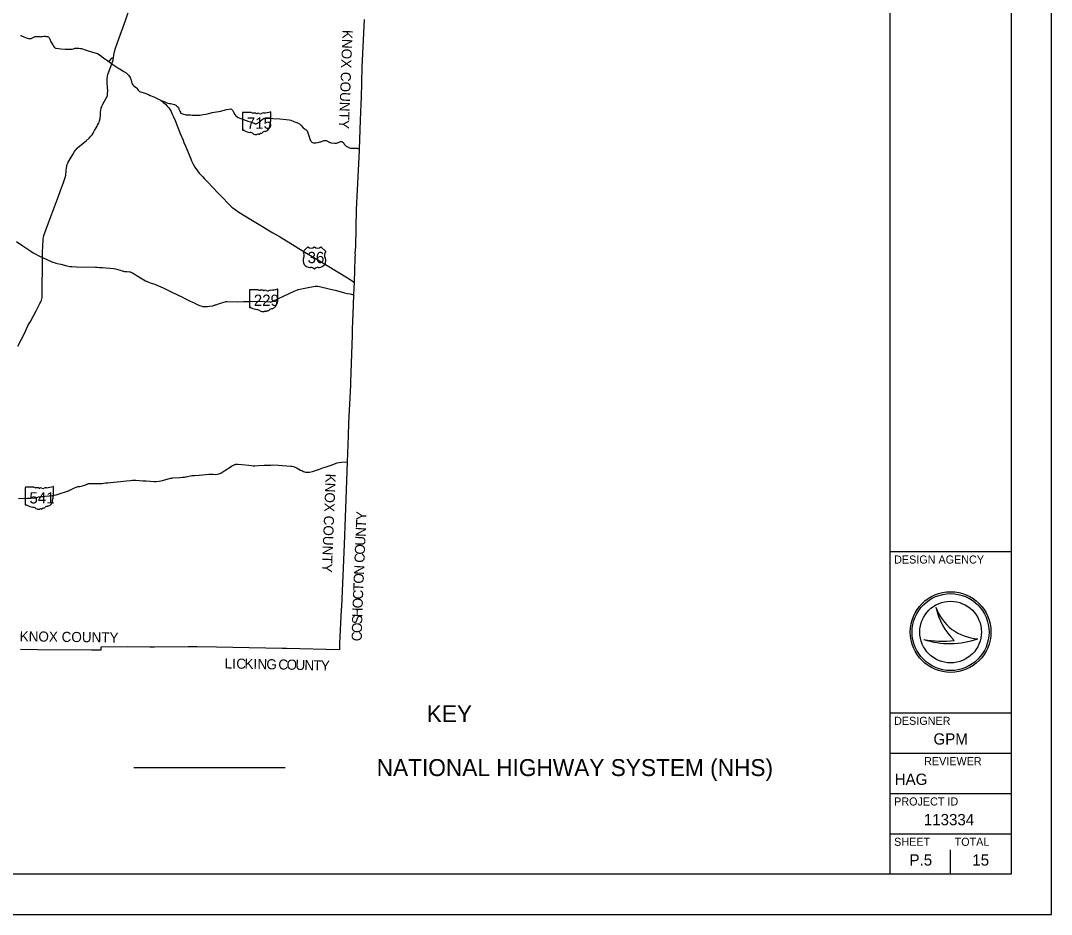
# Model space of a CAD drawing. Extents: x 1851937 to 2123937, y 78841 to 965467.
# Drawn here: x 2021685 to 2123937, y 789467 to 878119 of the extents above; entities that cross this region are included whole.
import ezdxf

# ---------------------------------------------------------------- set-up
doc = ezdxf.new("R2010")
doc.units = 0
for name, color, linetype in [('GM_X_County', 7, 'Continuous'), ('GM_X_County_Text', 7, 'Continuous'), ('GM_X_State_Location', 7, 'Continuous'), ('GM_X_State_Route', 7, 'Continuous'), ('GM_X_State_Shield', 7, 'Continuous'), ('GM_X_US_Location', 7, 'Continuous'), ('GM_X_US_Route', 7, 'Continuous'), ('GM_X_US_Shield', 7, 'Continuous'), ('SH_Border', 7, 'Continuous'), ('SH_Cut_Line', 7, 'Continuous'), ('SH_Data', 7, 'Continuous'), ('UT_P_Electric', 7, 'Continuous')]:
    doc.layers.add(name, color=color, linetype=linetype)

msp = doc.modelspace()

# ---------------------------------------------------------------- linework, layer by layer
at = {"layer": 'GM_X_County'}
msp.add_lwpolyline([(2055763, 878218), (2055528, 873511), (2055458, 870451), (2055436, 869891), (2055434, 869842), (2055375, 868236), (2055262, 865369), (2055260, 865250), (2054985, 859397), (2054895, 855723), (2054855, 855032), (2054877, 854884), (2054856, 854579), (2054855, 854554), (2054764, 852183), (2054712, 850926), (2054638, 848994), (2054606, 848369), (2054607, 848277), (2054583, 847562), (2054568, 846927), (2054408, 842255), (2054398, 841945), (2054221, 838228), (2054174, 836926), (2054094, 834355), (2053973, 831537), (2053891, 828875), (2053767, 826144), (2053518, 820007), (2053497, 819709), (2053322, 816320), (2053316, 815692), (2048065, 815838), (2047645, 815846), (2042723, 815938), (2041129, 815964), (2039196, 815994), (2038297, 816009), (2034983, 815969), (2034492, 815973), (2032252, 815993), (2029642, 815987), (2029630, 815668), (2029367, 815674), (2028708, 815664), (2023355, 815717), (2021673, 815746)], dxfattribs=at)
at = {"layer": 'GM_X_State_Route'}
msp.add_line((2052003, 866233), (2052042, 866219), dxfattribs=at)
for points in [[(2035622, 870200), (2035980, 870055), (2036138, 869993), (2036279, 869945), (2036417, 869913), (2036558, 869892), (2036695, 869872), (2036812, 869847), (2036953, 869792), (2037068, 869733), (2037193, 869644), (2037289, 869554), (2037333, 869488), (2037394, 869337), (2037480, 869134), (2037541, 869022), (2037562, 868988), (2037591, 868947), (2037634, 868917), (2037676, 868894), (2037828, 868834), (2037993, 868797), (2038083, 868790), (2038305, 868768), (2038542, 868758), (2038695, 868755), (2039115, 868743), (2039321, 868736), (2039479, 868750), (2039806, 868794), (2040101, 868837), (2040308, 868894), (2040463, 868945), (2040583, 868978), (2040689, 868997), (2040897, 869025), (2041337, 869092), (2041531, 869128), (2041735, 869189), (2041920, 869248), (2042003, 869277), (2042114, 869305), (2042363, 869352), (2042545, 869368)], [(2042545, 869368), (2042594, 869335), (2042642, 869290), (2042692, 869229), (2042775, 869098), (2042941, 868820), (2043046, 868684), (2043125, 868603), (2043165, 868565), (2043271, 868507), (2043441, 868437), (2043799, 868311), (2044072, 868207), (2044145, 868174)], [(2044145, 868174), (2044228, 868146), (2044485, 868066), (2044650, 868020), (2044748, 867974), (2044966, 867882), (2045049, 867884), (2045115, 867905), (2045347, 868044), (2045496, 868148), (2045657, 868302), (2045738, 868374), (2045780, 868397), (2045815, 868412), (2045863, 868423), (2045947, 868426), (2046333, 868432), (2046443, 868437), (2046694, 868418), (2047415, 868366), (2048030, 868319), (2048311, 868286), (2048478, 868237), (2048778, 868099), (2048964, 868039), (2049141, 867976), (2049274, 867922), (2049359, 867871), (2049472, 867746), (2049726, 867482), (2049814, 867406), (2049915, 867340), (2050017, 867279), (2050061, 867246), (2050096, 867193), (2050135, 867079), (2050331, 866489), (2050383, 866338), (2050436, 866237), (2050475, 866182), (2050522, 866127), (2050584, 866072), (2050651, 866031), (2050728, 866006), (2050822, 865996), (2050879, 865998), (2050960, 866010), (2051306, 866077), (2051387, 866092), (2051453, 866112), (2051589, 866162), (2051710, 866205), (2051772, 866223), (2051831, 866236), (2051890, 866242), (2051958, 866240), (2052003, 866233)], [(2052042, 866219), (2052077, 866207), (2052132, 866177), (2052188, 866133), (2052226, 866106), (2052260, 866081), (2052309, 866057), (2052356, 866039), (2052403, 866025), (2052481, 866008), (2052812, 865968), (2052913, 865962), (2052979, 865966), (2053034, 865976), (2053116, 865997), (2053426, 866114), (2053479, 866122), (2053566, 866119), (2053626, 866069), (2053679, 866020), (2053734, 865955), (2053794, 865862), (2053875, 865765), (2053976, 865673), (2054118, 865595), (2054322, 865511), (2054443, 865484), (2054558, 865484), (2054697, 865479), (2054909, 865475), (2055012, 865470), (2055069, 865457), (2055134, 865442), (2055263, 865366)], [(2021285, 856194), (2021906, 855784), (2022683, 855235), (2022919, 855090), (2023123, 854987), (2023488, 854802), (2023844, 854619)], [(2023844, 854619), (2024790, 854189), (2024894, 854148), (2025009, 854111), (2025183, 854074), (2025303, 854043), (2025690, 853958), (2026273, 853807), (2026552, 853731), (2026625, 853722), (2026751, 853716), (2027226, 853703), (2029102, 853652), (2029292, 853649)], [(2029292, 853649), (2029522, 853642), (2029816, 853631), (2030924, 853540), (2031100, 853511), (2031577, 853355), (2031749, 853299), (2031907, 853260), (2031995, 853249), (2032223, 853231), (2032440, 853215), (2032465, 853231), (2032563, 853189), (2032633, 853168), (2032697, 853141), (2032773, 853106), (2032940, 853009), (2033160, 852878), (2033740, 852518), (2034066, 852310), (2034317, 852203), (2034631, 852090), (2034990, 851965), (2035205, 851885), (2035600, 851702), (2035822, 851600), (2036739, 851166), (2037747, 850679), (2037983, 850558), (2038310, 850375), (2038448, 850310), (2038748, 850177), (2038912, 850117), (2039196, 849977), (2039309, 849934), (2039428, 849865), (2039572, 849817), (2039718, 849779), (2039844, 849748), (2040005, 849748), (2040213, 849751), (2040464, 849784), (2040747, 849839), (2041001, 849914), (2041048, 849930), (2041401, 850045), (2041852, 850201), (2041963, 850234), (2042035, 850243), (2042166, 850249), (2043216, 850231), (2043791, 850266), (2043860, 850260), (2044148, 850272), (2044402, 850274), (2045208, 850282), (2045895, 850266), (2046400, 850216), (2046520, 850227), (2046586, 850240), (2046717, 850278), (2048813, 851279), (2049136, 851424), (2049202, 851449), (2049254, 851457), (2049547, 851531), (2050057, 851624), (2050901, 851771), (2051075, 851783), (2051166, 851780), (2051337, 851749), (2052303, 851516), (2053025, 851339), (2053826, 851132), (2054114, 851058), (2054374, 851004), (2054713, 850923)], [(2029952, 832238), (2030108, 832256), (2030346, 832282), (2030597, 832307), (2031592, 832399), (2032180, 832461), (2032572, 832505), (2032800, 832522), (2032958, 832528), (2033117, 832530), (2033841, 832480), (2034136, 832461), (2034924, 832412), (2035163, 832410), (2035426, 832426), (2035761, 832494), (2036549, 832724), (2036702, 832748), (2036773, 832755), (2037484, 832806), (2037755, 832831), (2037951, 832850), (2038057, 832865), (2038195, 832895), (2038244, 832916), (2038536, 832971), (2038663, 832988), (2038861, 833008), (2038943, 833011), (2039387, 833039), (2040347, 833121), (2040792, 833119), (2040992, 833115), (2041217, 833138), (2041356, 833181), (2041442, 833206), (2041535, 833241), (2041735, 833349), (2042051, 833548), (2042460, 833818), (2042620, 833921), (2042711, 833981), (2042802, 834029), (2042869, 834062), (2042946, 834091), (2042980, 834103), (2043026, 834112), (2043117, 834118), (2043221, 834116), (2043634, 834075), (2044325, 834014), (2044549, 833991), (2044751, 833969), (2044931, 833965), (2045285, 833980), (2045854, 834016), (2046037, 834022), (2046308, 834034), (2046496, 834041), (2046698, 834045), (2047274, 834013), (2048444, 833936), (2048591, 833916), (2048718, 833892), (2048815, 833859), (2048914, 833819), (2049105, 833723), (2049296, 833623), (2049459, 833538), (2049642, 833451), (2049753, 833395), (2049838, 833365), (2049936, 833340), (2050041, 833326), (2050246, 833322), (2050341, 833331), (2050634, 833403), (2050835, 833470), (2051332, 833641), (2051649, 833755), (2051987, 833864), (2052501, 834035), (2053071, 834242), (2053272, 834299), (2053515, 834326), (2054095, 834352)], [(2021483, 830726), (2022343, 830751), (2022732, 830765), (2023046, 830784), (2023208, 830800), (2023489, 830872), (2023575, 830891), (2023687, 830908), (2023902, 830930), (2024112, 830941), (2024521, 830974), (2024839, 831012), (2025024, 831043), (2025228, 831086), (2025719, 831239), (2026154, 831378), (2026426, 831471), (2026582, 831537), (2027027, 831764)], [(2027027, 831764), (2027032, 831766), (2027197, 831849), (2027294, 831888), (2027353, 831903), (2027427, 831912), (2027560, 831920), (2027694, 831939), (2027839, 831969), (2028042, 832039), (2028415, 832198), (2028477, 832212), (2028581, 832220), (2028628, 832220), (2028803, 832220)], [(2028803, 832220), (2028974, 832217), (2029145, 832214), (2029319, 832215), (2029475, 832212), (2029785, 832219), (2029952, 832238)]]:
    msp.add_lwpolyline(points, dxfattribs=at)
at = {"layer": 'GM_X_State_Shield'}
for p, q in [((2043700, 868973), (2043700, 867272)), ((2044548, 869002), (2043727, 869002)), ((2046501, 868155), (2046501, 869045)), ((2046501, 868155), (2046501, 868155)), ((2044401, 851401), (2044401, 849699)), ((2045249, 851430), (2044428, 851430)), ((2047202, 850582), (2047202, 851472)), ((2047202, 850582), (2047202, 850582)), ((2022147, 831806), (2022147, 830105)), ((2022996, 831836), (2022175, 831836)), ((2024949, 830988), (2024949, 831878)), ((2024949, 830988), (2024949, 830988))]:
    msp.add_line(p, q, dxfattribs=at)
for centre, major_axis, start_param, end_param in [((2043732, 868977), (32.5, 0), 1.7126934, 3.2834897), ((2044743, 869200), (315, 0), 4.042523, 4.731795), ((2044848, 868047), (1130, 0), 1.4047578, 1.6578581), ((2045104, 868986), (90.8, 0), 3.8360951, 5.1854146), ((2045237, 868789), (189, 0), 0.950623, 2.079405), ((2045481, 869059), (227, 0), 4.0815608, 5.1457227), ((2045882, 868483), (598, 0), 1.6990114, 2.1078141), ((2045503, 871322), (2971, 0), 4.8143942, 5.0423688), ((2046494, 868089), (48.3, 0), 1.8839779, 3.6710726), ((2046470, 869048), (31.2, 0), 6.1411519, 7.9890352), ((2046468, 868151), (33.4, 0), 5.05454, 6.4181714), ((2043732, 867268), (32.7, 0), 3.00124, 4.5083009), ((2043737, 867442), (250, 0), 4.6659457, 4.8974612), ((2043788, 867174), (90.1, 0), 0.5192072, 1.6278991), ((2044926, 868702), (2146, 0), 4.1959971, 4.4889607), ((2045983, 866794), (407, 0), 1.6476453, 2.4884337), ((2045670, 867669), (743, 0), 5.1017525, 6.4400178), ((2046613, 867782), (211, 0), 2.3877238, 3.2625369), ((2046187, 867977), (290, 0), 5.9346948, 6.6959481), ((2044286, 866508), (671, 0), 0.8235189, 1.3235874), ((2045012, 867165), (426, 0), 4.0264811, 4.9967352), ((2045258, 866577), (350, 0), 1.495662, 1.9409797), ((2045289, 867038), (227, 0), 4.6910439, 5.5073738), ((2045495, 866873), (63.9, 0), 1.1475842, 2.3151517), ((2045468, 867107), (240, 0), 4.9370686, 5.64225), ((2044433, 851404), (32.5, 0), 1.7126934, 3.2834897), ((2045444, 851627), (315, 0), 4.042523, 4.731795), ((2045548, 850475), (1130, 0), 1.4047578, 1.6578581), ((2045805, 851413), (90.8, 0), 3.8360951, 5.1854146), ((2045938, 851216), (189, 0), 0.950623, 2.079405), ((2046182, 851486), (227, 0), 4.0815608, 5.1457227), ((2046583, 850910), (598, 0), 1.6990114, 2.1078141), ((2046204, 853749), (2971, 0), 4.8143942, 5.0423688), ((2047171, 851476), (31.2, 0), 6.1411519, 7.9890352), ((2046371, 850097), (743, 0), 5.1017525, 6.4400178), ((2047314, 850210), (211, 0), 2.3877238, 3.2625369), ((2047195, 850517), (48.3, 0), 1.8839779, 3.6710726), ((2046888, 850404), (290, 0), 5.9346948, 6.6959481), ((2047169, 850579), (33.4, 0), 5.05454, 6.4181714), ((2044433, 849696), (32.7, 0), 3.00124, 4.5083009), ((2044438, 849870), (250, 0), 4.6659457, 4.8974612), ((2044489, 849601), (90.1, 0), 0.5192072, 1.6278991), ((2045627, 851130), (2146, 0), 4.1959971, 4.4889607), ((2044987, 848935), (671, 0), 0.8235189, 1.3235874), ((2045713, 849593), (426, 0), 4.0264811, 4.9967352), ((2045959, 849005), (350, 0), 1.495662, 1.9409797), ((2045990, 849465), (227, 0), 4.6910439, 5.5073738), ((2046196, 849301), (63.9, 0), 1.1475842, 2.3151517), ((2046168, 849535), (240, 0), 4.9370686, 5.64225), ((2046684, 849222), (407, 0), 1.6476453, 2.4884337), ((2022180, 831810), (32.5, 0), 1.7126934, 3.2834897), ((2023191, 832033), (315, 0), 4.042523, 4.731795), ((2023295, 830881), (1130, 0), 1.4047578, 1.6578581), ((2023552, 831819), (90.8, 0), 3.8360951, 5.1854146), ((2023685, 831622), (189, 0), 0.950623, 2.079405), ((2023929, 831892), (227, 0), 4.0815608, 5.1457227), ((2024330, 831316), (598, 0), 1.6990114, 2.1078141), ((2023951, 834155), (2971, 0), 4.8143942, 5.0423688), ((2024918, 831882), (31.2, 0), 6.1411519, 7.9890352), ((2024118, 830502), (743, 0), 5.1017525, 6.4400178), ((2025061, 830616), (211, 0), 2.3877238, 3.2625369), ((2024942, 830923), (48.3, 0), 1.8839779, 3.6710726), ((2024635, 830810), (290, 0), 5.9346948, 6.6959481), ((2024916, 830985), (33.4, 0), 5.05454, 6.4181714), ((2022180, 830102), (32.7, 0), 3.00124, 4.5083009), ((2022185, 830276), (250, 0), 4.6659457, 4.8974612), ((2022236, 830007), (90.1, 0), 0.5192072, 1.6278991), ((2023374, 831536), (2146, 0), 4.1959971, 4.4889607), ((2022734, 829341), (671, 0), 0.8235189, 1.3235874), ((2023460, 829999), (426, 0), 4.0264811, 4.9967352), ((2023706, 829411), (350, 0), 1.495662, 1.9409797), ((2023737, 829871), (227, 0), 4.6910439, 5.5073738), ((2023943, 829707), (63.9, 0), 1.1475842, 2.3151517), ((2023915, 829940), (240, 0), 4.9370686, 5.64225), ((2024431, 829628), (407, 0), 1.6476453, 2.4884337)]:
    msp.add_ellipse(centre, major_axis=major_axis, ratio=0.8, start_param=start_param, end_param=end_param, dxfattribs=at)
at = {"layer": 'GM_X_US_Route'}
msp.add_line((2041509, 860781), (2041833, 860433), dxfattribs=at)
for points in [[(2031059, 875297), (2031061, 875302), (2031284, 875944), (2032076, 878119), (2032379, 879016)], [(2021662, 876636), (2021721, 876628), (2021785, 876616), (2021997, 876524), (2022342, 876374), (2022485, 876333), (2022568, 876323), (2022647, 876330), (2022740, 876355), (2023071, 876504), (2023145, 876534), (2023200, 876542), (2023265, 876546), (2023344, 876548), (2023575, 876535), (2023654, 876527), (2023729, 876530), (2023868, 876550), (2023997, 876569), (2024065, 876572), (2024110, 876569), (2024222, 876559), (2024344, 876530), (2024440, 876495), (2024492, 876457), (2024534, 876417), (2024567, 876361), (2024599, 876283), (2024688, 876026), (2024806, 875812), (2024875, 875703), (2024947, 875580), (2025001, 875498), (2025052, 875447), (2025109, 875410), (2025160, 875393), (2025213, 875383), (2025688, 875322), (2026107, 875292), (2026583, 875274), (2026695, 875271), (2026802, 875287), (2026918, 875325), (2027069, 875372), (2027179, 875385), (2027327, 875387), (2027461, 875375), (2027618, 875366), (2027738, 875345), (2027819, 875323), (2027983, 875262)], [(2030903, 874417), (2030946, 874697), (2030965, 874861), (2030988, 875011), (2031016, 875131), (2031059, 875297)], [(2027983, 875262), (2028077, 875227), (2028800, 874980), (2029174, 874884), (2029296, 874846), (2029385, 874810), (2029518, 874723), (2029736, 874558)], [(2029736, 874558), (2029954, 874397), (2030091, 874303), (2030205, 874224), (2030469, 874041), (2030511, 874010)], [(2030469, 874041), (2030576, 874186), (2030721, 874396), (2030738, 874413), (2030780, 874427), (2030835, 874424), (2030903, 874417)], [(2030726, 873828), (2030733, 873847), (2030857, 874188), (2030873, 874245), (2030903, 874417)], [(2030285, 872145), (2030281, 872272), (2030278, 872423), (2030290, 872543), (2030308, 872628), (2030344, 872768), (2030381, 872886), (2030726, 873828)], [(2030511, 874010), (2030583, 873957), (2030733, 873847), (2031436, 873383), (2031522, 873329)], [(2031522, 873329), (2031667, 873238), (2031938, 873080), (2032154, 872925), (2032420, 872665), (2032558, 872466), (2032646, 872214), (2032689, 872040), (2032724, 871927), (2032759, 871834), (2032808, 871752), (2032919, 871651), (2033061, 871552), (2033180, 871468), (2033238, 871407), (2033287, 871326), (2033354, 871209), (2033403, 871140), (2033489, 871080), (2033575, 871041), (2033705, 871009), (2033998, 870922), (2034361, 870777), (2034529, 870707), (2034905, 870545), (2035372, 870338), (2035622, 870200)], [(2029318, 867737), (2029412, 867909), (2029469, 868038), (2029519, 868179), (2029564, 868407), (2029597, 868756), (2029619, 869035), (2029645, 869225), (2029667, 869358), (2029692, 869467), (2029727, 869582), (2029770, 869691), (2029853, 869838), (2030187, 870433), (2030243, 870541), (2030289, 870681), (2030307, 870814), (2030324, 871192), (2030324, 871282), (2030318, 871362), (2030287, 872081), (2030285, 872145)], [(2035622, 870200), (2035872, 869998), (2036055, 869829), (2036235, 869640), (2036386, 869457), (2036506, 869278), (2036608, 869094), (2036699, 868905), (2036756, 868762), (2036812, 868628), (2037008, 868205), (2037510, 866924), (2037802, 866251), (2037890, 866034), (2038065, 865594), (2038290, 865049), (2038562, 864400), (2038640, 864213), (2038801, 863887), (2038983, 863580), (2039224, 863224), (2039403, 863002), (2039732, 862646), (2039927, 862440), (2040243, 862107), (2040744, 861581), (2041271, 861020), (2041509, 860781)], [(2023844, 854619), (2023850, 855183), (2023875, 855724), (2023908, 856371), (2023919, 856478), (2023943, 856611), (2023995, 856790), (2024231, 857449), (2024465, 858066), (2024765, 858844), (2025434, 860699), (2025634, 861264), (2025940, 862067), (2026120, 862561), (2026161, 862784), (2026204, 863295), (2026229, 863473), (2026255, 863652), (2026283, 863777), (2026340, 863918), (2026414, 864080), (2026869, 864851), (2027031, 865121), (2027099, 865229), (2027185, 865340), (2027265, 865427), (2027344, 865506), (2027736, 865824), (2028202, 866201), (2028471, 866451), (2028666, 866668), (2028769, 866797), (2028868, 866949), (2029014, 867216), (2029172, 867481)], [(2029172, 867481), (2029275, 867661), (2029318, 867737)], [(2041833, 860433), (2042141, 860112), (2042522, 859737), (2042643, 859627), (2042730, 859559), (2042956, 859370), (2043321, 859122), (2043935, 858748), (2044513, 858401), (2045688, 857689), (2046219, 857377), (2046718, 857073), (2047355, 856696), (2048936, 855736), (2049291, 855529), (2050061, 855062), (2050601, 854734), (2051347, 854288), (2052084, 853842), (2054110, 852617), (2054765, 852180)], [(2021421, 845836), (2022068, 847069), (2022278, 847551), (2022403, 847858), (2022439, 847929), (2022474, 847990), (2022532, 848078), (2022629, 848224), (2022689, 848316), (2022742, 848412), (2023222, 849335), (2023604, 850061), (2023662, 850170), (2023711, 850276), (2023758, 850401), (2023790, 850533), (2023809, 850673), (2023817, 850909), (2023831, 851404), (2023837, 851730), (2023865, 853646), (2023864, 853944), (2023857, 854259), (2023844, 854619)]]:
    msp.add_lwpolyline(points, dxfattribs=at)
at = {"layer": 'GM_X_US_Shield'}
for p, q in [((2050176, 855695), (2049709, 855228)), ((2051950, 855228), (2051483, 855695)), ((2050363, 853640), (2050456, 853640)), ((2051203, 853640), (2051296, 853640))]:
    msp.add_line(p, q, dxfattribs=at)
for centre, radius, start, end in [((2049173, 854853), 654, 334.54712, 35.00093), ((2050503, 856029), 467, 225.573, 314.427), ((2051156, 856029), 467, 225.573, 314.427), ((2052486, 854853), 654, 144.99907, 205.45288), ((2050355, 854294), 654, 154.83192, 270.63826), ((2051304, 854294), 654, 269.36174, 25.16808), ((2050456, 853173), 467, 36.8699, 90), ((2051203, 853173), 467, 90, 143.1301)]:
    msp.add_arc(centre, radius, start, end, dxfattribs=at)
at = {"layer": 'SH_Border'}
for p, q in [((2107937, 793467), (2107937, 961467)), ((2107937, 825467), (2119937, 825467)), ((2107937, 809467), (2119937, 809467)), ((2107937, 805467), (2119937, 805467)), ((2107937, 801467), (2119937, 801467)), ((2107937, 797467), (2119937, 797467))]:
    msp.add_line(p, q, dxfattribs=at)
msp.add_lwpolyline([(1863937, 961467), (2119937, 961467), (2119937, 793467), (1863937, 793467)], close=True, dxfattribs=at)
at = {"layer": 'SH_Cut_Line'}
msp.add_lwpolyline([(1851937, 789467), (2123937, 789467), (2123937, 965467), (1851937, 965467)], close=True, dxfattribs=at)
at = {"layer": 'SH_Data'}
for p, q in [((2112477, 819944), (2112477, 819944)), ((2113937, 817467), (2113937, 817467)), ((2111275, 816743), (2111275, 816743)), ((2116635, 816815), (2116636, 816815)), ((2113937, 793467), (2113937, 795867)), ((2110937, 794867), (2110937, 794867))]:
    msp.add_line(p, q, dxfattribs=at)
for radius in [4000, 3814, 3814, 3058]:
    msp.add_circle((2113937, 817467), radius, dxfattribs=at)
for centre, radius, start, end in [((2116865, 821448), 4639, 198.92567, 198.93195), ((2118711, 821228), 6365, 191.63793, 191.64215), ((2116865, 821448), 4639, 198.93195, 267.16574), ((2118711, 821228), 6365, 191.64215, 226.09467), ((2113853, 824427), 8105, 251.45764, 290.08324), ((2113121, 826702), 10128, 259.49639, 259.49952), ((2113853, 824427), 8105, 251.45274, 251.45764), ((2113121, 826702), 10128, 259.49952, 276.66723)]:
    msp.add_arc(centre, radius, start, end, dxfattribs=at)
at = {"layer": 'UT_P_Electric'}
msp.add_line((2032926, 804027), (2047926, 804027), dxfattribs=at)

# ---------------------------------------------------------------- texts
at = {"layer": 'GM_X_County_Text'}
for s, rotation, p in [('KNOX COUNTY', 267.8289, (2053620, 877211)), ('KNOX COUNTY', 267.71717, (2051952, 833195)), ('Y', 87.57765, (2055969, 828531)), ('T', 87.57747, (2055938, 827783)), ('N', 87.57765, (2055900, 826900)), ('U', 87.57765, (2055863, 826016)), ('C', 87.57735, (2055791, 824319)), ('O', 87.57821, (2055826, 825133)), ('O', 87.58091, (2055704, 822249)), ('N', 87.57873, (2055741, 823132)), ('T', 87.61951, (2055673, 821502)), ('C', 87.73455, (2055641, 820689)), ('O', 87.99332, (2055610, 819806)), ('S', 88.4429, (2055563, 818247)), ('H', 88.14677, (2055581, 818923)), ('O', 88.62214, (2055541, 817364)), ('KNOX COUNTY', 359.20933, (2021587, 816558)), ('C', 88.70029, (2055523, 816550)), ('L', 359.04675, (2041917, 813862)), ('I', 358.96503, (2042663, 813850)), ('C', 358.94354, (2043070, 813842)), ('K', 358.92618, (2043885, 813827)), ('I', 358.92369, (2044767, 813811)), ('N', 358.92127, (2045174, 813803)), ('G', 358.88587, (2046057, 813787)), ('C', 358.71051, (2047244, 813763)), ('O', 358.60959, (2048058, 813745)), ('U', 358.47227, (2048940, 813723)), ('N', 358.42486, (2049822, 813700)), ('T', 358.41862, (2050705, 813676)), ('Y', 358.41862, (2051451, 813655))]:
    msp.add_text(s, height=1000, rotation=rotation, dxfattribs=at).set_placement(p)
at = {"layer": 'GM_X_State_Location'}
msp.add_text('715', height=1, rotation=0.00001, dxfattribs=at).set_placement((2044729, 867703))
for s in ['s', 'r']:
    msp.add_text(s, height=1, dxfattribs=at).set_placement((2045082, 867776))
at = {"layer": 'GM_X_State_Shield'}
for s, p in [('715', (2044117, 867392)), ('229', (2044813, 849819)), ('541', (2022560, 830225))]:
    msp.add_text(s, height=1120.7, dxfattribs=at).set_placement(p)
at = {"layer": 'GM_X_US_Location'}
for s, p in [('0', (2025457, 860769)), ('/', (2025457, 860769)), ('0', (2052072, 853856)), ('/', (2052072, 853856))]:
    msp.add_text(s, height=1, dxfattribs=at).set_placement(p)
msp.add_text('36', height=1, rotation=0.00001, dxfattribs=at).set_placement((2051866, 853649))
at = {"layer": 'GM_X_US_Shield'}
msp.add_text('36', height=1120.7, dxfattribs=at).set_placement((2050146, 854061))
at = {"layer": 'SH_Data'}
for s, height, p in [('DESIGN AGENCY', 800, (2108337, 824267)), ('DESIGNER', 800, (2108337, 808267)), ('GPM', 1120, (2112244, 806307)), ('REVIEWER', 800, (2111312, 804267)), ('HAG', 1120, (2108391, 802307)), ('PROJECT ID', 800, (2108337, 800267)), ('113334', 1120, (2111281, 798307)), ('SHEET', 800, (2108337, 796267)), ('TOTAL', 800, (2114337, 796267)), ('P.5', 1120, (2109863, 794307)), ('15', 1120, (2116095, 794307))]:
    msp.add_text(s, height=height, dxfattribs=at).set_placement(p)
at = {"layer": 'UT_P_Electric'}
for s, p in [('KEY', (2061971, 808535)), ('NATIONAL HIGHWAY SYSTEM (NHS)', (2057006, 803187))]:
    msp.add_text(s, height=1680, dxfattribs=at).set_placement(p)

doc.saveas('drawing.dxf')
